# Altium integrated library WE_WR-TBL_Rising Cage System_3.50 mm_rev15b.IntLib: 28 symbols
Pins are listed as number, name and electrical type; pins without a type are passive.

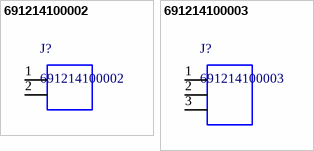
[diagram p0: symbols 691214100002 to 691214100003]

## 691214100002
designator J?
WR-TBL Terminal Blocks Serie 2141 - 3.50 mm; Manufacturer: Wurth Elektronik; ComponentLink1 Description: Manufacturer; ComponentLink2 Description: Datasheet
footprint 691214100002 (Serie 2141 - 3.50 mm _ 2 pins)
pins: 1, 2

## 691214100003
designator J?
WR-TBL Terminal Blocks Serie 2141 - 3.50 mm; Manufacturer: Wurth Elektronik; ComponentLink1 Description: Manufacturer; ComponentLink2 Description: Datasheet
footprint 691214100003 (Serie 2141 - 3.50 mm _ 3 pins)
pins: 1, 2, 3


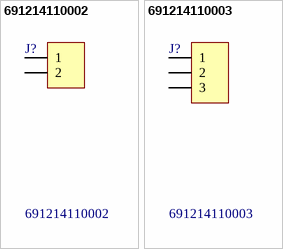
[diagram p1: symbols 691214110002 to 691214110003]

## 691214110002
designator J?
WR-TBL Terminal Blocks Serie 2141 - 3.50 mm with Rising Cage Clamp; Manufacturer: Würth Elektronik eiSos GmbH; ComponentLink1 Description: Manufacturer; ComponentLink2 Description: Datasheet; NoPins: 2
footprint 691214110002 (3,50mm - Horizontal wire entry - Rising cage clamp - 02p)
pins: 1, 2

## 691214110003
designator J?
WR-TBL Terminal Blocks Serie 2141 - 3.50 mm with Rising Cage Clamp; Manufacturer: Würth Elektronik eiSos GmbH; ComponentLink1 Description: Manufacturer; ComponentLink2 Description: Datasheet; NoPins: 3
footprint 691214110003 (3,50mm - Horizontal wire entry - Rising cage clamp - 03p)
pins: 1, 2, 3


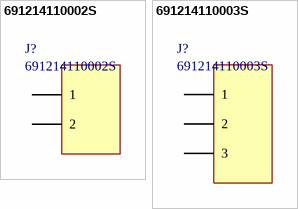
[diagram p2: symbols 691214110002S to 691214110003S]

## 691214110002S
designator J?
Horizontal Cable Entry with Rising Cage Clamp, Serie 2141S - 3.50 mm; Manufacturer: Wurth Elektronik; ComponentLink1 Description: Manufacturer; ComponentLink2 Description: Datasheet; NoPins: 2
footprint 691214110002S (Serie 2141S - 3.50 mm _ 2 pins)
pins: 1, 2

## 691214110003S
designator J?
Horizontal Cable Entry with Rising Cage Clamp, Serie 2141S - 3.50 mm; Manufacturer: Wurth Elektronik; ComponentLink1 Description: Manufacturer; ComponentLink2 Description: Datasheet; NoPins: 3
footprint 691214110003S (Serie 2141S - 3.50 mm _ 3 pins)
pins: 1, 2, 3


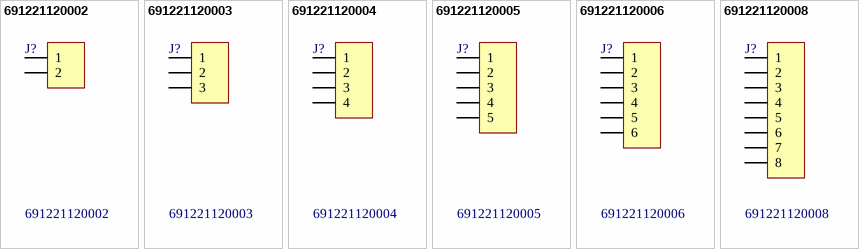
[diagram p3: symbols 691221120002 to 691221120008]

## 691221120002
designator J?
WR-TBL Terminal Blocks Serie 2211 - 3.50 mm; Manufacturer: Würth Elektronik eiSos GmbH; ComponentLink1 Description: Manufacturer; ComponentLink2 Description: Datasheet; NoPins: 2
footprint 691221120002 (3,50mm - modular - green - 55° wire entry - Cage clamp - 02p)
pins: 1, 2

## 691221120003
designator J?
WR-TBL Terminal Blocks Serie 2211 - 3.50 mm; Manufacturer: Würth Elektronik eiSos GmbH; ComponentLink1 Description: Manufacturer; ComponentLink2 Description: Datasheet; NoPins: 3
footprint 691221120003 (3,50mm - modular - green - 55° wire entry - Cage clamp - 03p)
pins: 1, 2, 3

## 691221120004
designator J?
WR-TBL Terminal Blocks Serie 2211 - 3.50 mm; Manufacturer: Würth Elektronik eiSos GmbH; ComponentLink1 Description: Manufacturer; ComponentLink2 Description: Datasheet; NoPins: 4
footprint 691221120004 (3,50mm - modular - green - 55° wire entry - Cage clamp - 04p)
pins: 1, 2, 3, 4

## 691221120005
designator J?
WR-TBL Terminal Blocks Serie 2211 - 3.50 mm; Manufacturer: Würth Elektronik eiSos GmbH; ComponentLink1 Description: Manufacturer; ComponentLink2 Description: Datasheet; NoPins: 5
footprint 691221120005 (3,50mm - modular - green - 55° wire entry - Cage clamp - 05p)
pins: 1, 2, 3, 4, 5

## 691221120006
designator J?
WR-TBL Terminal Blocks Serie 2211 - 3.50 mm; Manufacturer: Würth Elektronik eiSos GmbH; ComponentLink1 Description: Manufacturer; ComponentLink2 Description: Datasheet; NoPins: 6
footprint 691221120006 (3,50mm - modular - green - 55° wire entry - Cage clamp - 06p)
pins: 1, 2, 3, 4, 5, 6

## 691221120008
designator J?
WR-TBL Terminal Blocks Serie 2211 - 3.50 mm; Manufacturer: Würth Elektronik eiSos GmbH; ComponentLink1 Description: Manufacturer; ComponentLink2 Description: Datasheet; NoPins: 8
footprint 691221120008 (3,50mm - modular - green - 55° wire entry - Cage clamp - 08p)
pins: 1, 2, 3, 4, 5, 6, 7, 8


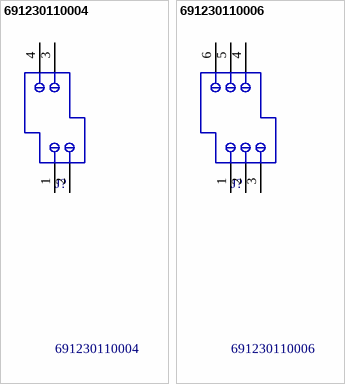
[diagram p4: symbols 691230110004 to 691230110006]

## 691230110004
designator J?
WR-TBL Terminal Blocks Serie 2301 - 3.50 mm with Rising Clamp; Manufacturer: Würth Elektronik eiSos GmbH; ComponentLink1 Description: Manufacturer; ComponentLink2 Description: Datasheet; NoPins: 4
footprint 691230110004 (3,50mm - modular - 2 rows - Right - horizontal entry with rising cage clamp - 04p)
pins: 1, 2, 3, 4

## 691230110006
designator J?
WR-TBL Terminal Blocks Serie 2301 - 3.50 mm with Rising Clamp; Manufacturer: Würth Elektronik eiSos GmbH; ComponentLink1 Description: Manufacturer; ComponentLink2 Description: Datasheet; NoPins: 6
footprint 691230110006 (3,50mm - modular - 2 rows - Right - horizontal entry with rising cage clamp - 06p)
pins: 1, 2, 3, 4, 5, 6


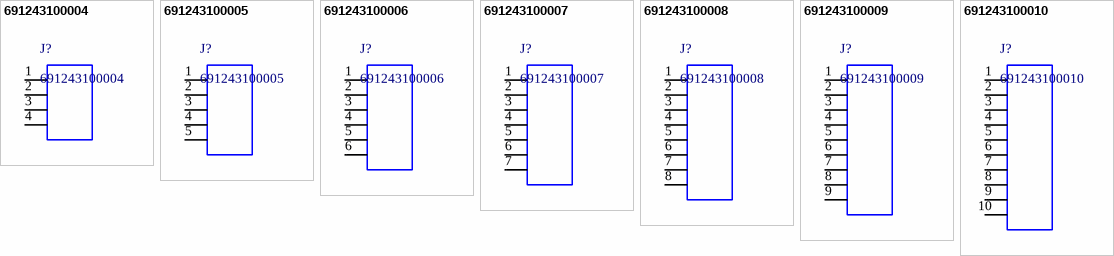
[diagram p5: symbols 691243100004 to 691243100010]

## 691243100004
designator J?
WR-TBL Terminal Blocks Serie 2431 - 3.50 mm; Manufacturer: Wurth Elektronik; ComponentLink1 Description: Manufacturer; ComponentLink2 Description: Datasheet
footprint 691243100004 (Serie 2431 - 3.50 mm _ 4 pins)
pins: 1, 2, 3, 4

## 691243100005
designator J?
WR-TBL Terminal Blocks Serie 2431 - 3.50 mm; Manufacturer: Wurth Elektronik; ComponentLink1 Description: Manufacturer; ComponentLink2 Description: Datasheet
footprint 691243100005 (Serie 2431 - 3.50 mm _ 5 pins)
pins: 1, 2, 3, 4, 5

## 691243100006
designator J?
WR-TBL Terminal Blocks Serie 2431 - 3.50 mm; Manufacturer: Wurth Elektronik; ComponentLink1 Description: Manufacturer; ComponentLink2 Description: Datasheet
footprint 691243100006 (Serie 2431 - 3.50 mm _ 6 pins)
pins: 1, 2, 3, 4, 5, 6

## 691243100007
designator J?
WR-TBL Terminal Blocks Serie 2431 - 3.50 mm; Manufacturer: Wurth Elektronik; ComponentLink1 Description: Manufacturer; ComponentLink2 Description: Datasheet
footprint 691243100007 (Serie 2431 - 3.50 mm _ 7 pins)
pins: 1, 2, 3, 4, 5, 6, 7

## 691243100008
designator J?
WR-TBL Terminal Blocks Serie 2431 - 3.50 mm; Manufacturer: Wurth Elektronik; ComponentLink1 Description: Manufacturer; ComponentLink2 Description: Datasheet
footprint 691243100008 (Serie 2431 - 3.50 mm _ 8 pins)
pins: 1, 2, 3, 4, 5, 6, 7, 8

## 691243100009
designator J?
WR-TBL Terminal Blocks Serie 2431 - 3.50 mm; Manufacturer: Wurth Elektronik; ComponentLink1 Description: Manufacturer; ComponentLink2 Description: Datasheet
footprint 691243100009 (Serie 2431 - 3.50 mm _ 9 pins)
pins: 1, 2, 3, 4, 5, 6, 7, 8, 9

## 691243100010
designator J?
WR-TBL Terminal Blocks Serie 2431 - 3.50 mm; Manufacturer: Wurth Elektronik; ComponentLink1 Description: Manufacturer; ComponentLink2 Description: Datasheet
footprint 691243100010 (Serie 2431 - 3.50 mm _ 10 pins)
pins: 1, 2, 3, 4, 5, 6, 7, 8, 9, 10


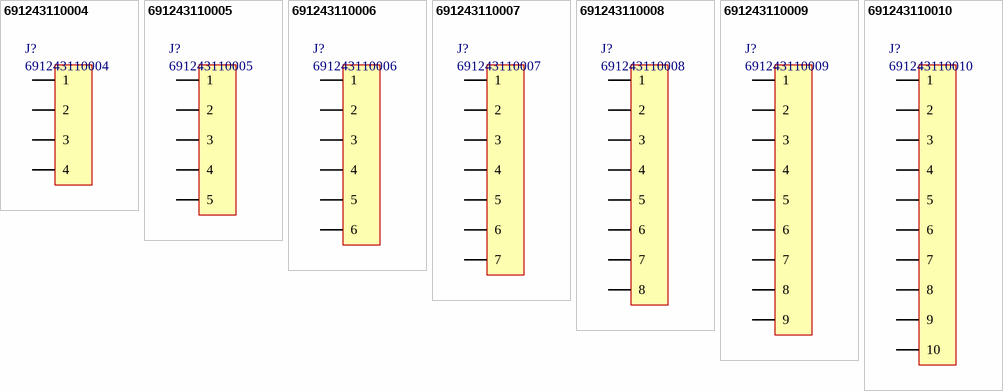
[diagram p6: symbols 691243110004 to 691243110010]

## 691243110004
designator J?
Horizontal Cable Entry with Rising Cage Clamp, Serie 2431 - 3.5 mm; Manufacturer: Wurth Elektronik; ComponentLink1 Description: Manufacturer; ComponentLink2 Description: Datasheet; NoPins: 4
footprint 691243110004 (Serie 2431 - 3.50 mm_4 pins)
pins: 1, 2, 3, 4

## 691243110005
designator J?
Horizontal Cable Entry with Rising Cage Clamp, Serie 2431 - 3.5 mm; Manufacturer: Wurth Elektronik; ComponentLink1 Description: Manufacturer; ComponentLink2 Description: Datasheet; NoPins: 5
footprint 691243110005 (Serie 2431 - 3.50 mm_5 pins)
pins: 1, 2, 3, 4, 5

## 691243110006
designator J?
Horizontal Cable Entry with Rising Cage Clamp, Serie 2431 - 3.5 mm; Manufacturer: Wurth Elektronik; ComponentLink1 Description: Manufacturer; ComponentLink2 Description: Datasheet; NoPins: 6
footprint 691243110006 (Serie 2431 - 3.50 mm_6 pins)
pins: 1, 2, 3, 4, 5, 6

## 691243110007
designator J?
Horizontal Cable Entry with Rising Cage Clamp, Serie 2431 - 3.5 mm; Manufacturer: Wurth Elektronik; ComponentLink1 Description: Manufacturer; ComponentLink2 Description: Datasheet; NoPins: 7
footprint 691243110007 (Serie 2431 - 3.50 mm_7 pins)
pins: 1, 2, 3, 4, 5, 6, 7

## 691243110008
designator J?
Horizontal Cable Entry with Rising Cage Clamp, Serie 2431 - 3.5 mm; Manufacturer: Wurth Elektronik; ComponentLink1 Description: Manufacturer; ComponentLink2 Description: Datasheet; NoPins: 8
footprint 691243110008 (Serie 2431 - 3.50 mm_8 pins)
pins: 1, 2, 3, 4, 5, 6, 7, 8

## 691243110009
designator J?
Horizontal Cable Entry with Rising Cage Clamp, Serie 2431 - 3.5 mm; Manufacturer: Wurth Elektronik; ComponentLink1 Description: Manufacturer; ComponentLink2 Description: Datasheet; NoPins: 9
footprint 691243110009 (Serie 2431 - 3.50 mm_9 pins)
pins: 1, 2, 3, 4, 5, 6, 7, 8, 9

## 691243110010
designator J?
Horizontal Cable Entry with Rising Cage Clamp, Serie 2431 - 3.5 mm; Manufacturer: Wurth Elektronik; ComponentLink1 Description: Manufacturer; ComponentLink2 Description: Datasheet; NoPins: 10
footprint 691243110010 (Serie 2431 - 3.50 mm_10 pins)
pins: 1, 2, 3, 4, 5, 6, 7, 8, 9, 10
